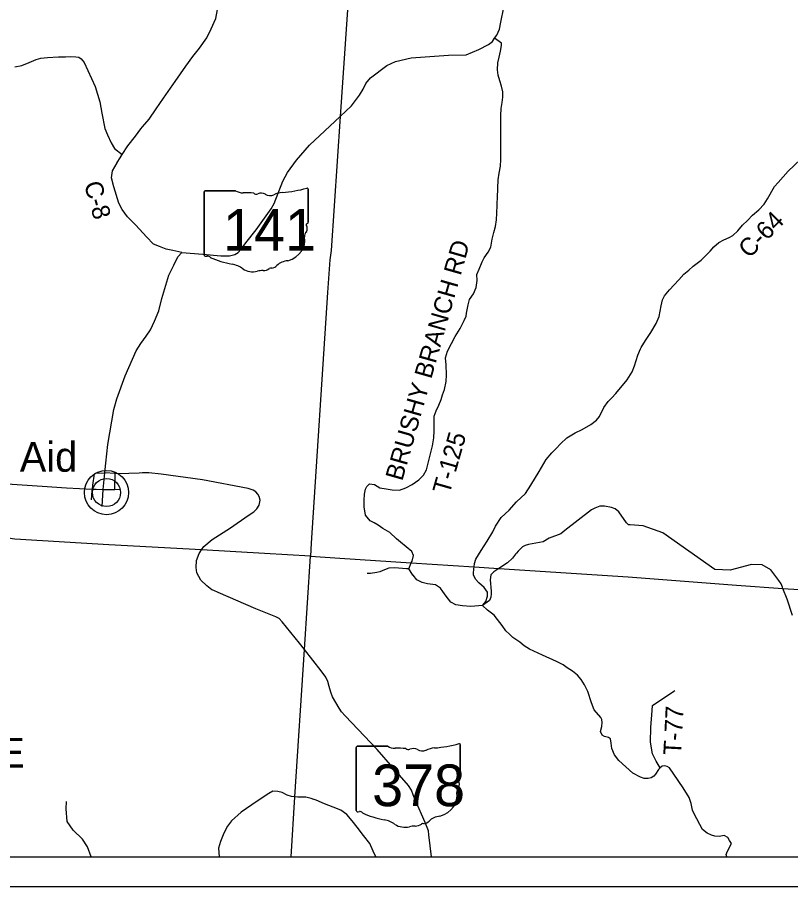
# Model space of a CAD drawing. Extents: x -6.4 to 34, y -1.2 to 22.
# Drawn here: x 3.618 to 6.219, y 14 to 16.922 of the extents above; entities that cross this region are included whole.
import ezdxf

# ---------------------------------------------------------------- set-up
doc = ezdxf.new("R2010")
doc.units = 0
for name, color, linetype in [('GM_X_County_Road', 7, 'Continuous'), ('GM_X_County_ROW', 7, 'Continuous'), ('GM_X_Minor_Lake', 7, 'Continuous'), ('GM_X_Minor_River', 7, 'Continuous'), ('GM_X_Minor_River_Text', 7, 'Continuous'), ('GM_X_Township', 7, 'Continuous'), ('GM_X_Township_Road', 7, 'Continuous'), ('GM_X_Township_Road_Text', 7, 'Continuous'), ('GM_X_Township_ROW', 7, 'Continuous'), ('GM_X_Township_Subdivision', 7, 'Continuous'), ('GM_X_Township_Subdivision_Text', 7, 'Continuous'), ('GM_X_Township_Text', 7, 'Continuous')]:
    doc.layers.add(name, color=color, linetype=linetype)

msp = doc.modelspace()

# ---------------------------------------------------------------- linework, layer by layer
at = {"layer": 'GM_X_County_Road'}
for radius in [0.0744, 0.0472]:
    msp.add_circle((3.9181, 15.3245), radius, dxfattribs=at)
at = {"layer": 'GM_X_County_ROW'}
for p, q in [((4.2463, 16.335), (4.2463, 16.1225)), ((4.3523, 16.3387), (4.2498, 16.3387)), ((4.5964, 16.2328), (4.5964, 16.344)), ((4.5964, 16.2328), (4.5964, 16.2328)), ((4.758, 14.468), (4.758, 14.2554)), ((4.8639, 14.4717), (4.7614, 14.4717)), ((5.108, 14.3657), (5.108, 14.4769)), ((5.108, 14.3658), (5.108, 14.3657))]:
    msp.add_line(p, q, dxfattribs=at)
for centre, major_axis, start_param, end_param in [((4.2503, 16.3355), (0.00406, 0), 1.712693, 3.28349), ((4.3767, 16.3634), (0.0393, 0), 4.042523, 4.731795), ((4.3898, 16.2194), (0.1412, 0), 1.404758, 1.657858), ((4.4385, 16.312), (0.0236, 0), 0.950623, 2.079405), ((4.5191, 16.2738), (0.0747, 0), 1.699011, 2.107814), ((4.4717, 16.6285), (0.3713, 0), 4.814394, 5.042369), ((4.5925, 16.3444), (0.0039, 0), 6.141152, 7.989035), ((4.4218, 16.3366), (0.0113, 0), 3.836095, 5.185415), ((4.4689, 16.3457), (0.0284, 0), 4.081561, 5.145723), ((4.5955, 16.2246), (0.00603, 0), 1.883978, 3.671073), ((4.5571, 16.2105), (0.0362, 0), 5.934695, 6.695948), ((4.5923, 16.2323), (0.00417, 0), 5.05454, 6.418171), ((4.6104, 16.1862), (0.0263, 0), 2.387724, 3.262537), ((4.4925, 16.1721), (0.0929, 0), 5.101752, 6.440018), ((4.2504, 16.122), (0.00409, 0), 3.00124, 4.508301), ((4.251, 16.1437), (0.0312, 0), 4.665946, 4.897461), ((4.2574, 16.1102), (0.0113, 0), 0.519207, 1.627899), ((4.3995, 16.3012), (0.2681, 0), 4.195997, 4.488961), ((4.5317, 16.0628), (0.0509, 0), 1.647645, 2.488434), ((4.3196, 16.027), (0.0839, 0), 0.823519, 1.323587), ((4.4103, 16.1091), (0.0532, 0), 4.026481, 4.996735), ((4.4411, 16.0356), (0.0437, 0), 1.495662, 1.94098), ((4.445, 16.0932), (0.0284, 0), 4.691044, 5.507374), ((4.4706, 16.0726), (0.00798, 0), 1.147584, 2.315152), ((4.4672, 16.1019), (0.03, 0), 4.937069, 5.64225), ((4.762, 14.4684), (0.00406, 0), 1.712693, 3.28349), ((4.8883, 14.4963), (0.0393, 0), 4.042523, 4.731795), ((4.9014, 14.3523), (0.1412, 0), 1.404758, 1.657858), ((4.9334, 14.4696), (0.0113, 0), 3.836095, 5.185415), ((4.9501, 14.445), (0.0236, 0), 0.950623, 2.079405), ((5.0307, 14.4067), (0.0747, 0), 1.699011, 2.107814), ((4.9833, 14.7615), (0.3713, 0), 4.814394, 5.042369), ((5.1042, 14.4774), (0.0039, 0), 6.141152, 7.989035), ((4.9806, 14.4787), (0.0284, 0), 4.081561, 5.145723), ((5.1071, 14.3576), (0.00603, 0), 1.883978, 3.671073), ((5.0688, 14.3435), (0.0362, 0), 5.934695, 6.695948), ((5.1039, 14.3653), (0.00417, 0), 5.05454, 6.418171), ((5.0041, 14.305), (0.0929, 0), 5.101752, 6.440018), ((5.122, 14.3192), (0.0263, 0), 2.387724, 3.262537), ((4.762, 14.255), (0.00409, 0), 3.00124, 4.508301), ((4.7626, 14.2767), (0.0312, 0), 4.665946, 4.897461), ((4.769, 14.2432), (0.0113, 0), 0.519207, 1.627899), ((4.9112, 14.4341), (0.2681, 0), 4.195997, 4.488961), ((5.0433, 14.1957), (0.0509, 0), 1.647645, 2.488434), ((4.8312, 14.1599), (0.0839, 0), 0.823519, 1.323587), ((4.922, 14.2421), (0.0532, 0), 4.026481, 4.996735), ((4.9527, 14.1686), (0.0437, 0), 1.495662, 1.94098), ((4.9566, 14.2262), (0.0284, 0), 4.691044, 5.507374), ((4.9823, 14.2056), (0.00798, 0), 1.147584, 2.315152), ((4.9788, 14.2348), (0.03, 0), 4.937069, 5.64225)]:
    msp.add_ellipse(centre, major_axis=major_axis, ratio=0.8, start_param=start_param, end_param=end_param, dxfattribs=at)
at = {"layer": 'GM_X_Minor_Lake'}
for points in [[(3.9072, 15.3345), (3.9072, 15.3345), (3.9118, 15.3905), (3.9153, 15.4231), (3.9227, 15.4855), (3.9429, 15.6034), (3.953, 15.6392), (3.9809, 15.7167), (4.0176, 15.8007), (4.0338, 15.8257), (4.0519, 15.8499), (4.0662, 15.8719), (4.0798, 15.9008), (4.094, 15.9349), (4.1046, 15.9768), (4.1276, 16.0551), (4.1441, 16.0885), (4.1577, 16.1169), (4.1718, 16.1317), (4.2417, 16.1257), (4.3026, 16.1199), (4.3322, 16.1199), (4.3497, 16.1251), (4.3613, 16.1316), (4.3714, 16.1428), (4.3864, 16.1636), (4.4217, 16.2075), (4.4718, 16.2779), (4.4817, 16.2958), (4.5114, 16.371), (4.5266, 16.4005), (4.5566, 16.4415), (4.6011, 16.4915), (4.704, 16.5887), (4.7423, 16.6248), (4.7691, 16.6605), (4.781, 16.6803), (4.7898, 16.6995), (4.8063, 16.7188), (4.8612, 16.7594), (4.8904, 16.7735), (4.9423, 16.7854), (5.0684, 16.7946), (5.1279, 16.796), (5.1704, 16.8131), (5.2024, 16.8305), (5.2159, 16.8404), (5.2234, 16.8516), (5.2313, 16.8616), (5.2394, 16.8822), (5.2446, 16.9056), (5.2543, 16.9547)], [(5.0108, 14.1), (5.002, 14.1738), (5.0005, 14.1872), (4.9899, 14.2155), (4.9574, 14.2889), (4.9495, 14.3081), (4.9439, 14.3238), (4.9333, 14.3404), (4.8282, 14.4609), (4.7209, 14.5739), (4.7088, 14.5871), (4.7004, 14.5998), (4.6779, 14.6376), (4.6723, 14.6534), (4.6668, 14.6729), (4.6619, 14.6889), (4.6551, 14.7043), (4.6401, 14.7256), (4.5837, 14.7973), (4.5672, 14.8182), (4.5089, 14.8904), (4.4989, 14.9009), (4.4877, 14.9069), (4.4199, 14.9341), (4.2932, 14.988), (4.2791, 14.9947), (4.2722, 14.998), (4.2552, 15.011), (4.2356, 15.0305), (4.2222, 15.0548), (4.2193, 15.0723), (4.2207, 15.0962), (4.2293, 15.1195), (4.2374, 15.1315), (4.2451, 15.143), (4.2738, 15.1669), (4.3351, 15.2062), (4.3946, 15.2468), (4.4131, 15.26), (4.4236, 15.2703), (4.4316, 15.2822), (4.4347, 15.2992), (4.4316, 15.3115), (4.4272, 15.3192), (4.4206, 15.3269), (4.4117, 15.3329), (4.394, 15.3379), (4.2405, 15.367), (4.1023, 15.3866), (4.06, 15.3908), (4.0387, 15.3902), (4.0278, 15.3898), (3.9587, 15.3874), (3.9468, 15.3882), (3.9118, 15.3905)], [(3.5665, 15.3546), (3.7016, 15.3459)], [(3.7016, 15.3459), (3.7836, 15.3406), (3.8706, 15.336), (3.8828, 15.3355), (3.9072, 15.3345)]]:
    msp.add_lwpolyline(points, dxfattribs=at)
at = {"layer": 'GM_X_Minor_River'}
for points in [[(4.0336, 16.5466), (4.0388, 16.5536), (4.0613, 16.5797), (4.0854, 16.6142), (4.1095, 16.6497), (4.1485, 16.7065), (4.1848, 16.7572), (4.2085, 16.7901), (4.231, 16.8177), (4.2555, 16.8525), (4.2704, 16.8828), (4.2862, 16.9173), (4.2952, 16.9655)], [(3.6096, 16.7552), (3.6327, 16.76), (3.6582, 16.7702), (3.6818, 16.7795), (3.6966, 16.7848), (3.7197, 16.7869), (3.7569, 16.7886), (3.7804, 16.7885), (3.7974, 16.7896), (3.8149, 16.7887), (3.8247, 16.7879), (3.8327, 16.7822), (3.8428, 16.7703), (3.8799, 16.6896), (3.8959, 16.6372), (3.8991, 16.6191)], [(3.8991, 16.6191), (3.9025, 16.5992), (3.9121, 16.5482), (3.9218, 16.5264), (3.9335, 16.4999), (3.9451, 16.4808), (3.9711, 16.461)], [(3.954, 16.4333), (3.9639, 16.45), (3.9711, 16.461), (3.9899, 16.4897), (4.0155, 16.5222), (4.0336, 16.5466), (4.0336, 16.5466)], [(4.1718, 16.1317), (4.1415, 16.1377), (4.1184, 16.142), (4.0957, 16.1512), (4.0764, 16.1596), (4.053, 16.1841), (4.0165, 16.2234), (3.9889, 16.2512), (3.9709, 16.2753), (3.9592, 16.2966), (3.9425, 16.3525), (3.9351, 16.3821), (3.9379, 16.4061), (3.9539, 16.4331), (3.954, 16.4333)], [(5.7143, 15.8076), (5.7144, 15.8078), (5.7163, 15.8125), (5.7312, 15.8359), (5.7484, 15.862), (5.7664, 15.8931), (5.7764, 15.9166), (5.783, 15.9522), (5.7881, 15.9723), (5.7946, 15.9852), (5.8118, 16.0056), (5.8434, 16.0397), (5.8602, 16.0582), (5.877, 16.0721), (5.8915, 16.085), (5.9185, 16.1053), (5.9483, 16.136), (5.9608, 16.1507), (5.9776, 16.1647), (5.994, 16.1741), (6.0126, 16.1812), (6.024, 16.1884), (6.0419, 16.2038), (6.0576, 16.2235), (6.074, 16.239), (6.0904, 16.2567), (6.1121, 16.2749), (6.13, 16.2941), (6.1415, 16.3116), (6.1645, 16.3532), (6.1774, 16.3668), (6.2103, 16.4042), (6.2518, 16.4439)], [(5.1525, 15.0518), (5.1525, 15.0521), (5.1536, 15.0684), (5.1541, 15.0746), (5.1552, 15.0862), (5.1598, 15.101), (5.1782, 15.1298), (5.1981, 15.1608), (5.2168, 15.1926), (5.2264, 15.2115), (5.2452, 15.2411), (5.2718, 15.2656), (5.2966, 15.2932), (5.3267, 15.3212), (5.3451, 15.3495), (5.373, 15.3957), (5.3972, 15.4355), (5.4159, 15.4574), (5.43, 15.4729), (5.4449, 15.4884), (5.4658, 15.5088), (5.4947, 15.525), (5.5179, 15.5359), (5.5465, 15.5528), (5.5659, 15.5683), (5.5762, 15.5796), (5.5911, 15.6099), (5.6053, 15.63), (5.6179, 15.6428), (5.6316, 15.6576), (5.6694, 15.7037), (5.6858, 15.7298), (5.6939, 15.7503), (5.7055, 15.7863), (5.7143, 15.8076)], [(6.0042, 14.1), (6.0021, 14.1076), (6.0067, 14.1193), (6.0197, 14.1447), (6.0137, 14.1546), (6.0077, 14.1649), (5.9956, 14.1718), (5.9786, 14.1689), (5.9645, 14.1697), (5.9524, 14.1732), (5.9384, 14.1797), (5.9229, 14.1923), (5.8944, 14.2441), (5.8892, 14.2567), (5.884, 14.2788), (5.8777, 14.2993), (5.8574, 14.3317), (5.8258, 14.3774), (5.8115, 14.3988), (5.8032, 14.4038), (5.7956, 14.4061), (5.7869, 14.405), (5.7804, 14.3988), (5.775, 14.3937), (5.764, 14.3781), (5.759, 14.3713), (5.7502, 14.3661), (5.74, 14.3631), (5.7263, 14.3635), (5.7135, 14.3674), (5.6878, 14.3812), (5.6406, 14.4236), (5.6263, 14.4434), (5.6173, 14.4644), (5.6155, 14.4826), (5.6129, 14.4963), (5.6065, 14.5016), (5.5933, 14.5044), (5.585, 14.5086), (5.579, 14.5215), (5.5836, 14.5386), (5.5856, 14.5515), (5.5841, 14.5618), (5.5804, 14.5686), (5.5578, 14.5946), (5.5488, 14.6178), (5.5365, 14.6558), (5.5252, 14.6787), (5.5143, 14.6958), (5.5019, 14.7103), (5.4857, 14.7245), (5.4672, 14.7356), (5.4539, 14.7451), (5.432, 14.7566), (5.3844, 14.7774), (5.3409, 14.7985), (5.3227, 14.8092), (5.3084, 14.8211), (5.285, 14.8368), (5.2733, 14.8486), (5.2616, 14.8597), (5.2484, 14.8776), (5.2334, 14.8974), (5.2221, 14.9119), (5.2126, 14.9192), (5.1994, 14.9295), (5.1821, 14.9448), (5.1935, 14.9588), (5.1993, 14.9766), (5.199, 14.9899), (5.1885, 15.0055), (5.1707, 15.0212), (5.1591, 15.0334), (5.1523, 15.0482), (5.1525, 15.0518)]]:
    msp.add_lwpolyline(points, dxfattribs=at)
at = {"layer": 'GM_X_Minor_River_Text'}
for points in [[(5.2339, 16.3409), (5.2339, 16.341), (5.2343, 16.347), (5.2356, 16.3754), (5.2384, 16.3974), (5.2435, 16.421), (5.2443, 16.4434), (5.2438, 16.4855), (5.2445, 16.5379), (5.2439, 16.5675), (5.2437, 16.5915), (5.2449, 16.6158), (5.2492, 16.6359), (5.2508, 16.653), (5.2505, 16.6712), (5.2469, 16.6898), (5.2405, 16.7085), (5.2349, 16.7275), (5.2331, 16.7453), (5.2337, 16.7685), (5.2387, 16.7878), (5.2434, 16.8083), (5.2461, 16.8265), (5.2469, 16.8349), (5.2234, 16.8516)], [(4.9345, 15.068), (4.9432, 15.0884), (4.9455, 15.0938), (4.9506, 15.1127), (4.9453, 15.1264), (4.9257, 15.1425), (4.9068, 15.1581), (4.8929, 15.1685), (4.8706, 15.1902), (4.8476, 15.204), (4.8317, 15.2143), (4.8181, 15.2224), (4.8049, 15.2293), (4.7887, 15.2484), (4.7847, 15.2761), (4.7844, 15.2993), (4.7853, 15.3186), (4.7892, 15.3361), (4.7934, 15.3452), (4.8021, 15.3542), (4.8188, 15.3519), (4.8377, 15.3408), (4.8589, 15.3372), (4.8786, 15.3337), (4.9029, 15.3321), (4.9245, 15.3399), (4.9462, 15.3512), (4.9683, 15.3667), (4.9839, 15.3829), (4.9939, 15.4003), (5.0024, 15.4322), (5.009, 15.4588), (5.0141, 15.4811), (5.0188, 15.5084), (5.0204, 15.5324), (5.0202, 15.5567), (5.0203, 15.5814), (5.0265, 15.5988), (5.0361, 15.6181), (5.0434, 15.6367), (5.048, 15.653), (5.0549, 15.6712), (5.0604, 15.6981), (5.062, 15.7205), (5.0603, 15.7536), (5.0578, 15.7771), (5.0648, 15.8002), (5.0782, 15.8249), (5.0912, 15.8491), (5.1073, 15.8763), (5.1214, 15.9032), (5.1276, 15.9169), (5.1284, 15.9279), (5.1343, 15.9552), (5.1393, 15.9734), (5.1519, 15.9927), (5.1615, 16.0132), (5.1643, 16.0367), (5.164, 16.0568), (5.1717, 16.0758), (5.1814, 16.1), (5.1886, 16.1137), (5.2016, 16.1322), (5.2101, 16.1492), (5.2148, 16.1762), (5.2206, 16.1986), (5.2264, 16.2183), (5.2292, 16.2414), (5.2304, 16.2634), (5.2321, 16.29), (5.2327, 16.3223), (5.2339, 16.3409)], [(3.9463, 15.3351), (3.9468, 15.3882)], [(6.1915, 15.0062), (6.1871, 15.0177), (6.1792, 15.0284), (6.1521, 15.065), (6.123, 15.0816), (6.0873, 15.0828), (6.0151, 15.0634), (5.9645, 15.0657), (5.7891, 15.1889), (5.7228, 15.2128), (5.6791, 15.2157), (5.6742, 15.2165), (5.6674, 15.2232), (5.6408, 15.2598), (5.6288, 15.2701), (5.616, 15.2741), (5.5928, 15.2786), (5.5767, 15.2785), (5.5599, 15.2718), (5.5488, 15.266), (5.4595, 15.1974), (5.4458, 15.1861), (5.4065, 15.171), (5.3862, 15.1592), (5.3369, 15.1501), (5.3263, 15.1461), (5.3169, 15.1422), (5.3021, 15.1279), (5.2968, 15.1211)], [(5.2968, 15.1211), (5.294, 15.1176), (5.2836, 15.1044), (5.2669, 15.0885), (5.2376, 15.0692), (5.2207, 15.0581), (5.2102, 15.0484), (5.208, 15.0313), (5.2118, 14.993), (5.2114, 14.9841), (5.2107, 14.9732), (5.2057, 14.9611), (5.1821, 14.9448)], [(4.8454, 15.0614), (4.8371, 15.0583), (4.8269, 15.0563), (4.8064, 15.0522), (4.7961, 15.0522), (4.7945, 15.0524)], [(4.9489, 15.0463), (4.9483, 15.047), (4.9393, 15.0611), (4.9345, 15.068), (4.9271, 15.0686), (4.8866, 15.0717), (4.8679, 15.0707), (4.8535, 15.0645), (4.8454, 15.0614)], [(5.1821, 14.9448), (5.143, 14.9412), (5.1157, 14.9432), (5.093, 14.9468), (5.0759, 14.956), (5.0601, 14.9758), (5.0496, 14.9922), (5.041, 15.0036), (5.0247, 15.0147), (4.9978, 15.0172), (4.9793, 15.0226), (4.9619, 15.0314), (4.9489, 15.0463)], [(6.2253, 14.9114), (6.207, 14.9657), (6.1929, 15.0025), (6.1915, 15.0062)], [(5.7804, 14.3988), (5.7669, 14.4214), (5.7549, 14.4462), (5.7475, 14.485), (5.7493, 14.5343), (5.753, 14.592), (5.7539, 14.6091), (5.8266, 14.657), (5.8295, 14.6588)], [(4.616, 14.293), (4.6157, 14.2931), (4.6059, 14.2964), (4.5885, 14.3007), (4.5612, 14.3012), (4.5516, 14.3018), (4.5399, 14.3025), (4.5259, 14.3079), (4.5093, 14.3167), (4.4945, 14.3198), (4.4778, 14.3206), (4.4642, 14.3135), (4.4242, 14.2875), (4.3713, 14.2505), (4.3385, 14.2207), (4.3244, 14.2029), (4.3129, 14.1802), (4.3013, 14.1521), (4.2948, 14.1294), (4.2966, 14.1)], [(4.8236, 14.1), (4.8236, 14.1), (4.8149, 14.1191), (4.8033, 14.145), (4.7819, 14.1717), (4.7608, 14.1995), (4.7438, 14.2212), (4.7265, 14.2422), (4.7061, 14.2564), (4.68, 14.2668), (4.6509, 14.2787), (4.6229, 14.2906), (4.616, 14.293)], [(3.8663, 14.1), (3.8546, 14.1339), (3.8369, 14.1591), (3.8063, 14.1896), (3.7853, 14.2194), (3.7821, 14.2612), (3.7836, 14.2858)]]:
    msp.add_lwpolyline(points, dxfattribs=at)
at = {"layer": 'GM_X_Township'}
for p, q in [((2.1, 14.1), (8.9, 14.1)), ((2, 14), (9, 14))]:
    msp.add_line(p, q, dxfattribs=at)
at = {"layer": 'GM_X_Township_Road'}
for p, q in [((4.2463, 16.1225), (4.2463, 16.335)), ((4.2498, 16.3387), (4.3523, 16.3387)), ((4.5964, 16.344), (4.5964, 16.2328)), ((4.5937, 16.2292), (4.5937, 16.2292)), ((4.7579, 14.2554), (4.7579, 14.468)), ((4.7614, 14.4717), (4.8639, 14.4717)), ((5.108, 14.4769), (5.108, 14.3657)), ((5.1053, 14.3622), (5.1053, 14.3622))]:
    msp.add_line(p, q, dxfattribs=at)
for centre, major_axis, start_param, end_param in [((4.2503, 16.3355), (0.00406, 0), 1.712693, 3.28349), ((4.3767, 16.3634), (0.0393, 0), 4.042523, 4.731795), ((4.3898, 16.2194), (0.1412, 0), 1.404758, 1.657858), ((4.4385, 16.312), (0.0236, 0), 0.950623, 2.079405), ((4.5191, 16.2738), (0.0747, 0), 1.699011, 2.107814), ((4.4717, 16.6285), (0.3713, 0), 4.814394, 5.042369), ((4.5925, 16.3444), (0.0039, 0), 6.141152, 7.989035), ((4.4218, 16.3366), (0.0113, 0), 3.836095, 5.185415), ((4.4689, 16.3457), (0.0284, 0), 4.081561, 5.145723), ((4.5955, 16.2246), (0.00603, 0), 1.883978, 3.671073), ((4.5571, 16.2105), (0.0362, 0), 5.934695, 6.695948), ((4.5923, 16.2323), (0.00417, 0), 5.05454, 6.418171), ((4.6104, 16.1862), (0.0263, 0), 2.387724, 3.262537), ((4.4925, 16.1721), (0.0929, 0), 5.101752, 6.440018), ((4.2504, 16.122), (0.00409, 0), 3.00124, 4.508301), ((4.251, 16.1437), (0.0312, 0), 4.665946, 4.897461), ((4.2574, 16.1102), (0.0113, 0), 0.519207, 1.627899), ((4.3995, 16.3012), (0.2681, 0), 4.195997, 4.488961), ((4.5317, 16.0628), (0.0509, 0), 1.647645, 2.488434), ((4.3196, 16.027), (0.0839, 0), 0.823519, 1.323587), ((4.4103, 16.1091), (0.0532, 0), 4.026481, 4.996735), ((4.4411, 16.0356), (0.0437, 0), 1.495662, 1.94098), ((4.445, 16.0932), (0.0284, 0), 4.691044, 5.507374), ((4.4706, 16.0726), (0.00798, 0), 1.147584, 2.315152), ((4.4672, 16.1019), (0.03, 0), 4.937069, 5.64225), ((4.762, 14.4684), (0.00406, 0), 1.712693, 3.28349), ((4.8883, 14.4963), (0.0393, 0), 4.042523, 4.731795), ((4.9014, 14.3523), (0.1412, 0), 1.404758, 1.657858), ((4.9334, 14.4696), (0.0113, 0), 3.836095, 5.185415), ((4.9501, 14.445), (0.0236, 0), 0.950623, 2.079405), ((5.0307, 14.4067), (0.0747, 0), 1.699011, 2.107814), ((4.9833, 14.7615), (0.3713, 0), 4.814394, 5.042369), ((5.1042, 14.4774), (0.0039, 0), 6.141152, 7.989035), ((4.9806, 14.4787), (0.0284, 0), 4.081561, 5.145723), ((5.1071, 14.3576), (0.00603, 0), 1.883978, 3.671073), ((5.0688, 14.3435), (0.0362, 0), 5.934695, 6.695948), ((5.1039, 14.3653), (0.00417, 0), 5.05454, 6.418171), ((5.0041, 14.305), (0.0929, 0), 5.101752, 6.440018), ((5.122, 14.3192), (0.0263, 0), 2.387724, 3.262537), ((4.762, 14.255), (0.00409, 0), 3.00124, 4.508301), ((4.7626, 14.2767), (0.0312, 0), 4.665946, 4.897461), ((4.769, 14.2432), (0.0113, 0), 0.519207, 1.627899), ((4.9112, 14.4341), (0.2681, 0), 4.195997, 4.488961), ((5.0433, 14.1957), (0.0509, 0), 1.647645, 2.488434), ((4.8312, 14.1599), (0.0839, 0), 0.823519, 1.323587), ((4.922, 14.2421), (0.0532, 0), 4.026481, 4.996735), ((4.9527, 14.1686), (0.0437, 0), 1.495662, 1.94098), ((4.9566, 14.2262), (0.0284, 0), 4.691044, 5.507374), ((4.9823, 14.2056), (0.00798, 0), 1.147584, 2.315152), ((4.9788, 14.2348), (0.03, 0), 4.937069, 5.64225)]:
    msp.add_ellipse(centre, major_axis=major_axis, ratio=0.8, start_param=start_param, end_param=end_param, dxfattribs=at)
at = {"layer": 'GM_X_Township_Road_Text'}
for points in [[(3.8702, 15.3308), (3.8706, 15.336), (3.8716, 15.3496), (3.8775, 15.3879), (3.8809, 15.3893), (3.9118, 15.3905)], [(3.8679, 15.3002), (3.8702, 15.3308)], [(3.9031, 15.2776), (3.9072, 15.3345)], [(3.9072, 15.3345), (3.9393, 15.335)], [(3.9393, 15.335), (3.9463, 15.3351), (3.9633, 15.3354)]]:
    msp.add_lwpolyline(points, dxfattribs=at)
at = {"layer": 'GM_X_Township_ROW'}
for points in [[(4.7383, 17.0951), (4.704, 16.5887), (4.6735, 16.1378), (4.6688, 16.1067), (4.6617, 15.9964), (4.6068, 15.1539), (4.6039, 15.1106), (4.4494, 15.1194), (4.2374, 15.1315), (3.9258, 15.1493), (3.6093, 15.1673), (3.5571, 15.1752), (3.5118, 15.1797), (3.2794, 15.1952), (2.59, 15.2415), (2.4159, 15.2489), (2.1, 15.2699)], [(4.5386, 14.1), (4.5516, 14.3018), (4.5837, 14.7973), (4.6039, 15.1106), (4.7025, 15.1042), (4.9432, 15.0884), (5.1541, 15.0746), (5.2376, 15.0692), (5.6728, 15.0407), (6.0364, 15.013), (6.1929, 15.0025), (6.375, 14.9903), (6.7178, 14.9672), (7.6051, 14.9095), (7.6512, 14.9069), (8.0847, 14.8753), (8.8343, 14.8293), (8.9, 14.8252)]]:
    msp.add_lwpolyline(points, dxfattribs=at)

# ---------------------------------------------------------------- texts
at = {"layer": 'GM_X_County_Road'}
msp.add_text('Aid', height=0.1, dxfattribs=at).set_placement((3.6263, 15.3945))
at = {"layer": 'GM_X_County_ROW'}
for s, p in [('141', (4.3102, 16.1375)), ('378', (4.8114, 14.2704))]:
    msp.add_text(s, height=0.14004, dxfattribs=at).set_placement(p)
at = {"layer": 'GM_X_Township_Subdivision'}
for s, rotation, p in [('BRUSHY BRANCH RD', 74.1328, (4.9126, 15.3608)), ('T-125', 74.1328, (5.0713, 15.3157)), ('T-77', 87.0579, (5.8505, 14.4406))]:
    msp.add_text(s, height=0.06, rotation=rotation, dxfattribs=at).set_placement(p)
at = {"layer": 'GM_X_Township_Subdivision_Text'}
msp.add_text('LAWRENCE', height=0.1, dxfattribs=at).set_placement((2.8854, 14.4))
at = {"layer": 'GM_X_Township_Text'}
for s, rotation, p in [('C-8', 285.7699, (3.8416, 16.3619)), ('C-64', 45.7104, (6.08, 16.1091))]:
    msp.add_text(s, height=0.06, rotation=rotation, dxfattribs=at).set_placement(p)

doc.saveas('drawing.dxf')
